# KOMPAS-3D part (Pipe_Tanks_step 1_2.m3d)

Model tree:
1. X Axis
2. Y Axis
3. Z Axis  (labels: Bend 90 Dn 50; Pipe Dn 50; T-Bend Dn 50; C:\Program Files\ASCON\KOMPAS-3D V10\Sys\graphic.lyt)
     Òîëùèíà ñòåíêè 1 = 1

Referenced files in C:\Documents and Settings\kashirsky\Мои документы\Camtasia Studio\Pipelines3D\Tanks\: Tanks_step 1.a3d, Tanks_step 1.spw
Referenced files in C:\Documents and Settings\kashirsky\Мои документы\Camtasia Studio\Pipelines3D\Tanks\Tanks_step 1_Pipes\: Pipe_Tanks_step 1_2.m3d
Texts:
  Pipe Dn 50
  Steel ASTM A295
  Three Point Plane
  Plane at Angle
  Line and Point Plane
  Axis through Two Vertices
  Axis of Feature
  Axis of Conical Surface
  Axis through Edge
  Trim by Surface
  Trim by Sketch
  Feature with No History
  Intersection Axis of Two Planes
  Two Line Plane
  Line and Face Plane
  Bend by line
  Hole in sheet body
  Cut in sheet body
  Point in CM
  Linear Dimension from Line to Point
  Surface Finish Symbol
  Geometric Tolerance Symbol
  Leader #1
  Leader #2
  Leader #3
  Shape Deviations and Datum
  Node point number
  Mark of coordination axis
  Node point designation
  Mark/Reference designation with leader
  Mark/reference designation on line
  Mark/Reference designation without leader
  Bend 90 Dn 50
  T-Bend Dn 50
  Plane of section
